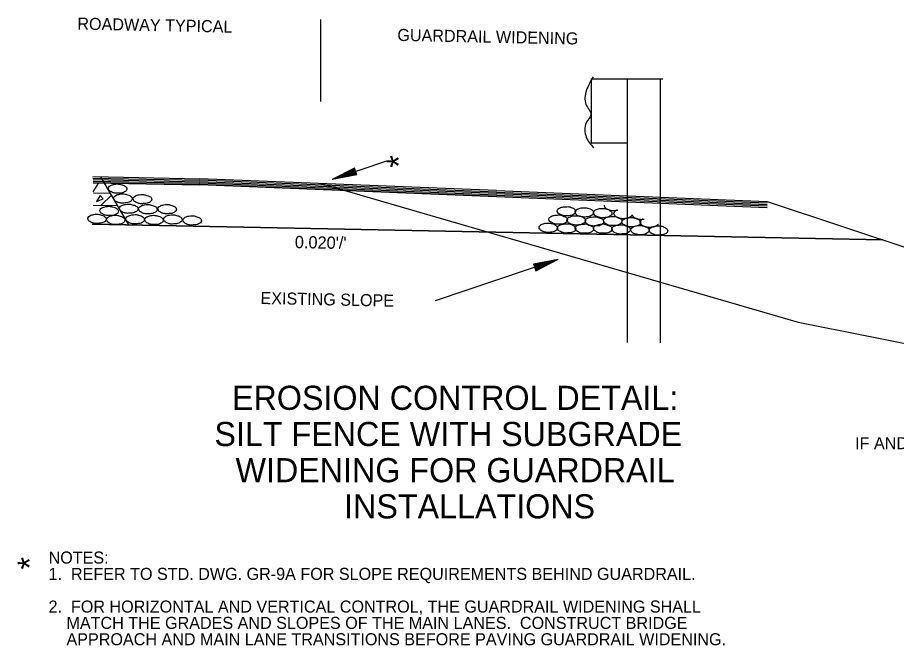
# Model space of a CAD drawing. Extents: x 1929624 to 1932070, y 596315 to 605533.
# Drawn here: x 1930679.3 to 1931116.5, y 605210.4 to 605522.8 of the extents above; entities that cross this region are included whole.
import ezdxf

# ---------------------------------------------------------------- set-up
doc = ezdxf.new("R2010")
doc.units = 0
doc.layers.add('Default', color=7, linetype='Continuous')
doc.layers.add('R_Border', color=7, linetype='Continuous')

msp = doc.modelspace()

# ---------------------------------------------------------------- linework, layer by layer
at = {"layer": 'Default'}
for p, q in [((1930964.72, 605492.28), (1930964.72, 605460.45)), ((1930964.72, 605492.28), (1931000.37, 605492.28)), ((1930982.56, 605492.28), (1930982.56, 605361.1)), ((1930998.94, 605492.14), (1930998.94, 605360.97)), ((1930964.72, 605460.45), (1930982.56, 605460.45)), ((1930862.9, 605451.4), (1930835.81, 605442.2)), ((1930846.84, 605447.99), (1930835.81, 605442.2)), ((1930846.97, 605447.71), (1930837.74, 605442.86)), ((1930847.08, 605447.37), (1930839.81, 605443.6)), ((1930848.05, 605444.54), (1930846.84, 605447.99)), ((1930716.81, 605443.72), (1930769.98, 605442.66)), ((1930716.81, 605442.98), (1930769.98, 605441.92)), ((1930734.6, 605419.73), (1930720.77, 605443.63)), ((1930848.05, 605444.54), (1930835.81, 605442.2)), ((1930847.97, 605444.8), (1930837.74, 605442.86)), ((1930847.83, 605445.12), (1930839.81, 605443.6)), ((1930847.13, 605447.1), (1930841.73, 605444.26)), ((1930847.73, 605445.42), (1930841.73, 605444.26)), ((1930847.25, 605446.84), (1930843.66, 605444.95)), ((1930847.61, 605445.73), (1930843.66, 605444.95)), ((1930847.34, 605446.53), (1930845.62, 605445.64)), ((1930847.57, 605446.03), (1930845.62, 605445.64)), ((1930716.84, 605442.24), (1930769.98, 605441.18)), ((1930716.86, 605441.5), (1930769.98, 605440.44)), ((1930716.89, 605440.76), (1930769.93, 605439.71)), ((1930716.89, 605440.67), (1930769.98, 605439.61)), ((1930716.98, 605436.19), (1930719.64, 605440.64)), ((1930917.5, 605433.8), (1930769.88, 605439.71)), ((1930917.55, 605435.28), (1930769.93, 605441.18)), ((1930917.55, 605434.54), (1930769.93, 605440.44)), ((1930917.6, 605436.75), (1930769.98, 605442.66)), ((1930917.6, 605436.02), (1930769.98, 605441.92)), ((1930917.5, 605433.7), (1930769.98, 605439.61)), ((1930717.01, 605435.6), (1930725.52, 605435.43)), ((1930720.87, 605429.47), (1930726.1, 605434.42)), ((1930917.5, 605434.54), (1931052.16, 605429.15)), ((1930917.54, 605435.28), (1931052.19, 605429.89)), ((1930917.56, 605436.02), (1931052.22, 605430.63)), ((1930917.6, 605436.75), (1931052.26, 605431.37)), ((1930917.48, 605433.8), (1931052.14, 605428.41)), ((1931052.26, 605431.37), (1931287.27, 605353.24)), ((1930716.89, 605429.55), (1930729.06, 605429.31)), ((1930887.28, 605381.99), (1930948.19, 605402.67)), ((1930935.95, 605400.34), (1930948.19, 605402.67)), ((1930935.95, 605400.34), (1930937.16, 605396.88)), ((1930936.03, 605400.08), (1930946.26, 605402.01)), ((1930936.17, 605399.76), (1930944.19, 605401.28)), ((1930936.27, 605399.46), (1930942.27, 605400.61)), ((1930936.39, 605399.14), (1930940.34, 605399.93)), ((1930936.43, 605398.84), (1930938.38, 605399.24)), ((1930936.66, 605398.34), (1930938.38, 605399.24)), ((1930936.75, 605398.04), (1930940.34, 605399.93)), ((1930936.87, 605397.78), (1930942.27, 605400.61)), ((1930936.92, 605397.5), (1930944.19, 605401.28)), ((1930937.03, 605397.17), (1930946.26, 605402.01)), ((1930937.16, 605396.88), (1930948.19, 605402.67))]:
    msp.add_line(p, q, dxfattribs=at)
msp.add_lwpolyline([(1930718.62, 605431.33), (1930721.86, 605432.66), (1930720.39, 605434.24), (1930718.62, 605431.33)], dxfattribs=at)
for points in [[(1930965.58, 605493.32), (1930962.23, 605486.4), (1930962.06, 605479.66), (1930964.47, 605474.47), (1930962.23, 605470.53), (1930962.23, 605463.28), (1930965.78, 605458.04)], [(1930729.05, 605440.07), (1930727.42, 605439.87), (1930725.55, 605439.28), (1930724.62, 605438.44), (1930724.47, 605437.85), (1930724.91, 605436.87), (1930725.46, 605436.38), (1930726.54, 605435.79), (1930728.11, 605435.44), (1930728.9, 605435.44), (1930730.13, 605435.49), (1930731.46, 605435.64), (1930732.54, 605436.08), (1930733.53, 605436.97), (1930733.67, 605437.56), (1930733.38, 605438.44), (1930732.64, 605439.03), (1930731.9, 605439.38), (1930730.82, 605439.72), (1930730.08, 605439.92), (1930729.05, 605440.07)], [(1930731.72, 605435.18), (1930730.1, 605434.98), (1930728.23, 605434.39), (1930727.24, 605433.56), (1930727.1, 605432.96), (1930727.54, 605431.98), (1930728.08, 605431.49), (1930729.16, 605430.9), (1930730.74, 605430.55), (1930731.57, 605430.55), (1930732.8, 605430.6), (1930734.13, 605430.75), (1930735.17, 605431.19), (1930736.2, 605432.08), (1930736.35, 605432.67), (1930736.05, 605433.56), (1930735.31, 605434.15), (1930734.58, 605434.49), (1930733.44, 605434.83), (1930732.75, 605435.03), (1930731.72, 605435.18)], [(1930741.38, 605434.86), (1930739.76, 605434.66), (1930737.89, 605434.07), (1930736.9, 605433.24), (1930736.76, 605432.64), (1930737.2, 605431.66), (1930737.74, 605431.17), (1930738.82, 605430.58), (1930740.4, 605430.23), (1930741.23, 605430.23), (1930742.47, 605430.28), (1930743.79, 605430.43), (1930744.83, 605430.87), (1930745.86, 605431.76), (1930746.01, 605432.35), (1930745.71, 605433.24), (1930744.97, 605433.83), (1930744.24, 605434.17), (1930743.1, 605434.51), (1930742.42, 605434.71), (1930741.38, 605434.86)], [(1930734.58, 605430.06), (1930732.96, 605429.86), (1930731.09, 605429.27), (1930730.11, 605428.44), (1930729.96, 605427.9), (1930730.4, 605426.91), (1930730.94, 605426.37), (1930732.02, 605425.78), (1930733.6, 605425.44), (1930734.44, 605425.44), (1930735.67, 605425.49), (1930736.99, 605425.63), (1930738.03, 605426.12), (1930739.06, 605426.96), (1930739.21, 605427.6), (1930738.91, 605428.49), (1930738.18, 605429.08), (1930737.44, 605429.42), (1930736.31, 605429.72), (1930735.62, 605429.96), (1930734.58, 605430.06)], [(1930744.1, 605429.84), (1930742.47, 605429.64), (1930740.6, 605429.05), (1930739.62, 605428.22), (1930739.47, 605427.67), (1930739.91, 605426.69), (1930740.46, 605426.15), (1930741.54, 605425.56), (1930743.11, 605425.21), (1930743.95, 605425.21), (1930745.18, 605425.26), (1930746.51, 605425.41), (1930747.54, 605425.9), (1930748.58, 605426.74), (1930748.72, 605427.38), (1930748.43, 605428.27), (1930747.69, 605428.86), (1930746.95, 605429.2), (1930745.82, 605429.5), (1930745.13, 605429.74), (1930744.1, 605429.84)], [(1930753.68, 605429.86), (1930752.05, 605429.66), (1930750.18, 605429.07), (1930749.25, 605428.23), (1930749.1, 605427.69), (1930749.54, 605426.71), (1930750.08, 605426.17), (1930751.17, 605425.58), (1930752.74, 605425.23), (1930753.53, 605425.23), (1930754.76, 605425.28), (1930756.09, 605425.43), (1930757.17, 605425.92), (1930758.15, 605426.76), (1930758.3, 605427.4), (1930758.01, 605428.28), (1930757.27, 605428.87), (1930756.53, 605429.22), (1930755.45, 605429.51), (1930754.71, 605429.76), (1930753.68, 605429.86)], [(1930724.82, 605428.97), (1930723.19, 605428.77), (1930721.32, 605428.18), (1930720.39, 605427.35), (1930720.24, 605426.76), (1930720.68, 605425.77), (1930721.22, 605425.28), (1930722.31, 605424.69), (1930723.88, 605424.35), (1930724.67, 605424.35), (1930725.9, 605424.39), (1930727.23, 605424.54), (1930728.31, 605424.98), (1930729.29, 605425.87), (1930729.44, 605426.46), (1930729.15, 605427.35), (1930728.41, 605427.94), (1930727.67, 605428.28), (1930726.59, 605428.63), (1930725.85, 605428.82), (1930724.82, 605428.97)], [(1930952.47, 605428.74), (1930950.84, 605428.64), (1930948.87, 605428.05), (1930947.84, 605427.12), (1930947.69, 605426.58), (1930948.19, 605425.59), (1930948.78, 605425.15), (1930949.91, 605424.61), (1930951.48, 605424.16), (1930952.32, 605424.16), (1930953.5, 605424.26), (1930954.83, 605424.41), (1930955.86, 605424.8), (1930956.75, 605425.64), (1930956.9, 605426.28), (1930956.6, 605427.17), (1930955.96, 605427.76), (1930955.27, 605428.15), (1930954.19, 605428.59), (1930953.5, 605428.74), (1930952.47, 605428.74)], [(1930961.28, 605428.22), (1930959.66, 605428.12), (1930957.74, 605427.43), (1930956.76, 605426.64), (1930956.61, 605426.1), (1930957.15, 605425.07), (1930957.59, 605424.53), (1930958.77, 605424.03), (1930960.25, 605423.69), (1930961.09, 605423.59), (1930962.32, 605423.64), (1930963.69, 605423.89), (1930964.68, 605424.33), (1930965.71, 605425.12), (1930965.86, 605425.76), (1930965.56, 605426.64), (1930964.83, 605427.28), (1930964.09, 605427.63), (1930963.01, 605427.97), (1930962.32, 605428.12), (1930961.28, 605428.22)], [(1930970.46, 605427.85), (1930968.84, 605427.8), (1930966.87, 605427.11), (1930965.88, 605426.22), (1930965.74, 605425.63), (1930966.28, 605424.65), (1930966.82, 605424.21), (1930967.9, 605423.71), (1930969.48, 605423.27), (1930970.31, 605423.22), (1930971.49, 605423.32), (1930972.82, 605423.57), (1930973.86, 605423.96), (1930974.84, 605424.75), (1930974.99, 605425.34), (1930974.69, 605426.22), (1930973.95, 605426.81), (1930973.26, 605427.31), (1930972.18, 605427.65), (1930971.49, 605427.8), (1930970.46, 605427.85)], [(1930971.08, 605429.44), (1930971.08, 605429.41), (1930971.08, 605429.34), (1930971.08, 605429.27), (1930971.16, 605429.01), (1930971.27, 605428.74), (1930971.43, 605428.49), (1930971.52, 605428.36), (1930971.63, 605428.24), (1930971.88, 605427.99), (1930972.17, 605427.8), (1930972.43, 605427.65), (1930972.7, 605427.52), (1930972.97, 605427.41), (1930973.25, 605427.31), (1930974.03, 605427.08), (1930974.82, 605426.91), (1930975.24, 605426.84), (1930975.45, 605426.82), (1930975.66, 605426.81), (1930976.25, 605426.84), (1930976.55, 605426.87), (1930976.84, 605426.91), (1930977.36, 605426.99), (1930977.88, 605427.09)], [(1930977.74, 605427.14), (1930977.44, 605427.02), (1930977.2, 605426.91), (1930976.96, 605426.79), (1930976.67, 605426.61), (1930976.41, 605426.39), (1930976.19, 605426.14), (1930976.08, 605426), (1930975.97, 605425.85), (1930975.9, 605425.72), (1930975.84, 605425.58), (1930975.82, 605425.45), (1930975.82, 605425.38), (1930975.83, 605425.31), (1930975.9, 605425.04), (1930976.02, 605424.78), (1930976.17, 605424.52), (1930976.27, 605424.4), (1930976.37, 605424.28), (1930976.62, 605424.03), (1930976.91, 605423.84), (1930977.17, 605423.69), (1930977.44, 605423.56), (1930977.71, 605423.44), (1930977.99, 605423.34), (1930978.77, 605423.12), (1930979.57, 605422.95), (1930980.4, 605422.85), (1930980.55, 605422.85), (1930980.7, 605422.86), (1930980.99, 605422.88), (1930981.58, 605422.95), (1930981.92, 605423), (1930982.25, 605423.06), (1930982.58, 605423.12), (1930982.91, 605423.2), (1930983.18, 605423.27), (1930983.44, 605423.36), (1930983.69, 605423.47), (1930983.94, 605423.59), (1930984.22, 605423.74), (1930984.48, 605423.9), (1930984.71, 605424.11), (1930984.82, 605424.24), (1930984.93, 605424.38), (1930985, 605424.5), (1930985.04, 605424.62)], [(1930718.79, 605425.06), (1930717.16, 605424.86), (1930715.29, 605424.27), (1930714.36, 605423.43), (1930714.21, 605422.84), (1930714.65, 605421.86), (1930715.2, 605421.37), (1930716.28, 605420.78), (1930717.85, 605420.43), (1930718.64, 605420.43), (1930719.87, 605420.48), (1930721.2, 605420.63), (1930722.28, 605421.07), (1930723.27, 605421.96), (1930723.41, 605422.55), (1930723.12, 605423.43), (1930722.38, 605424.03), (1930721.64, 605424.37), (1930720.56, 605424.71), (1930719.82, 605424.91), (1930718.79, 605425.06)], [(1930728.1, 605424.53), (1930726.47, 605424.33), (1930724.6, 605423.74), (1930723.67, 605422.9), (1930723.52, 605422.31), (1930723.96, 605421.33), (1930724.5, 605420.84), (1930725.59, 605420.24), (1930727.16, 605419.9), (1930727.95, 605419.9), (1930729.18, 605419.95), (1930730.51, 605420.1), (1930731.59, 605420.54), (1930732.57, 605421.43), (1930732.72, 605422.02), (1930732.43, 605422.9), (1930731.69, 605423.49), (1930730.95, 605423.84), (1930729.87, 605424.18), (1930729.13, 605424.38), (1930728.1, 605424.53)], [(1930737.74, 605424.85), (1930736.12, 605424.65), (1930734.25, 605424.06), (1930733.31, 605423.22), (1930733.16, 605422.63), (1930733.61, 605421.65), (1930734.15, 605421.15), (1930735.23, 605420.56), (1930736.81, 605420.22), (1930737.59, 605420.22), (1930738.82, 605420.27), (1930740.15, 605420.42), (1930741.23, 605420.86), (1930742.22, 605421.75), (1930742.37, 605422.34), (1930742.07, 605423.22), (1930741.33, 605423.81), (1930740.6, 605424.16), (1930739.51, 605424.5), (1930738.77, 605424.7), (1930737.74, 605424.85)], [(1930747.14, 605424.48), (1930745.52, 605424.29), (1930743.65, 605423.7), (1930742.71, 605422.86), (1930742.56, 605422.27), (1930743.01, 605421.29), (1930743.55, 605420.79), (1930744.63, 605420.2), (1930746.2, 605419.86), (1930746.99, 605419.86), (1930748.22, 605419.91), (1930749.55, 605420.06), (1930750.63, 605420.5), (1930751.62, 605421.38), (1930751.77, 605421.97), (1930751.47, 605422.86), (1930750.73, 605423.45), (1930749.99, 605423.8), (1930748.91, 605424.14), (1930748.17, 605424.34), (1930747.14, 605424.48)], [(1930756.51, 605424.75), (1930754.89, 605424.55), (1930753.02, 605423.96), (1930752.09, 605423.12), (1930751.94, 605422.58), (1930752.38, 605421.6), (1930752.92, 605421.06), (1930754, 605420.47), (1930755.58, 605420.12), (1930756.37, 605420.12), (1930757.6, 605420.17), (1930758.93, 605420.32), (1930760.01, 605420.81), (1930760.99, 605421.65), (1930761.14, 605422.29), (1930760.84, 605423.17), (1930760.11, 605423.76), (1930759.37, 605424.11), (1930758.29, 605424.4), (1930757.55, 605424.65), (1930756.51, 605424.75)], [(1930766.16, 605424.24), (1930764.53, 605424.04), (1930762.66, 605423.45), (1930761.73, 605422.61), (1930761.58, 605422.07), (1930762.03, 605421.09), (1930762.57, 605420.55), (1930763.65, 605419.96), (1930765.22, 605419.61), (1930766.01, 605419.61), (1930767.24, 605419.66), (1930768.57, 605419.81), (1930769.65, 605420.3), (1930770.64, 605421.14), (1930770.78, 605421.78), (1930770.49, 605422.66), (1930769.75, 605423.25), (1930769.01, 605423.6), (1930767.93, 605423.89), (1930767.19, 605424.14), (1930766.16, 605424.24)], [(1930948.39, 605424.63), (1930946.67, 605424.44), (1930944.75, 605423.94), (1930943.76, 605423.01), (1930943.62, 605422.47), (1930944.11, 605421.43), (1930944.7, 605420.99), (1930945.78, 605420.4), (1930947.36, 605420.01), (1930948.14, 605420.01), (1930949.37, 605420.11), (1930950.75, 605420.2), (1930951.79, 605420.7), (1930952.67, 605421.53), (1930952.82, 605422.17), (1930952.52, 605423.06), (1930951.79, 605423.65), (1930951.1, 605423.94), (1930950.01, 605424.39), (1930949.37, 605424.58), (1930948.39, 605424.63)], [(1930957.32, 605424.21), (1930955.7, 605424.16), (1930953.73, 605423.53), (1930952.75, 605422.59), (1930952.6, 605422.05), (1930953.14, 605421.02), (1930953.68, 605420.57), (1930954.76, 605420.08), (1930956.34, 605419.69), (1930957.17, 605419.59), (1930958.35, 605419.69), (1930959.68, 605419.93), (1930960.72, 605420.33), (1930961.7, 605421.11), (1930961.85, 605421.75), (1930961.55, 605422.64), (1930960.82, 605423.23), (1930960.13, 605423.67), (1930959.04, 605424.02), (1930958.35, 605424.16), (1930957.32, 605424.21)], [(1930966.42, 605423.71), (1930964.79, 605423.57), (1930962.82, 605423.02), (1930961.79, 605422.09), (1930961.64, 605421.55), (1930962.18, 605420.56), (1930962.73, 605420.12), (1930963.86, 605419.48), (1930965.38, 605419.14), (1930966.22, 605419.14), (1930967.4, 605419.24), (1930968.83, 605419.28), (1930969.81, 605419.78), (1930970.75, 605420.61), (1930970.89, 605421.25), (1930970.6, 605422.14), (1930969.91, 605422.73), (1930969.17, 605423.07), (1930968.14, 605423.42), (1930967.45, 605423.71), (1930966.42, 605423.71)], [(1930975.37, 605423.94), (1930973.75, 605423.75), (1930971.83, 605423.25), (1930970.85, 605422.32), (1930970.7, 605421.78), (1930971.24, 605420.74), (1930971.78, 605420.3), (1930972.86, 605419.71), (1930974.44, 605419.32), (1930975.22, 605419.32), (1930976.46, 605419.42), (1930977.78, 605419.51), (1930978.87, 605420.01), (1930979.8, 605420.84), (1930979.95, 605421.48), (1930979.65, 605422.37), (1930978.92, 605422.96), (1930978.18, 605423.25), (1930977.14, 605423.75), (1930976.41, 605423.89), (1930975.37, 605423.94)], [(1930984.67, 605423.3), (1930983.05, 605423.25), (1930981.08, 605422.61), (1930980.1, 605421.68), (1930979.95, 605421.14), (1930980.49, 605420.11), (1930981.03, 605419.66), (1930982.11, 605419.17), (1930983.69, 605418.78), (1930984.53, 605418.68), (1930985.71, 605418.78), (1930987.03, 605419.02), (1930988.07, 605419.42), (1930989.05, 605420.2), (1930989.2, 605420.84), (1930988.9, 605421.73), (1930988.17, 605422.32), (1930987.48, 605422.76), (1930986.39, 605423.11), (1930985.71, 605423.25), (1930984.67, 605423.3)], [(1930984.99, 605424.64), (1930985.08, 605424.43), (1930985.19, 605424.23), (1930985.32, 605424.04), (1930985.47, 605423.85), (1930985.73, 605423.6), (1930986.01, 605423.41), (1930986.27, 605423.27), (1930986.54, 605423.13), (1930986.81, 605423.02), (1930987.09, 605422.92), (1930987.87, 605422.7), (1930988.67, 605422.52), (1930989.09, 605422.46), (1930989.29, 605422.43), (1930989.5, 605422.43), (1930990.09, 605422.45), (1930990.68, 605422.52), (1930990.99, 605422.57)], [(1930990.57, 605422.71), (1930990.31, 605422.59), (1930990.18, 605422.53), (1930990.04, 605422.46), (1930989.75, 605422.27), (1930989.5, 605422.06), (1930989.27, 605421.81), (1930989.16, 605421.67), (1930989.06, 605421.52), (1930988.98, 605421.39), (1930988.93, 605421.25), (1930988.91, 605421.11), (1930988.9, 605421.05), (1930988.91, 605420.98), (1930988.99, 605420.71), (1930989.1, 605420.45), (1930989.26, 605420.19), (1930989.35, 605420.07), (1930989.45, 605419.95), (1930989.71, 605419.7), (1930989.99, 605419.51), (1930990.26, 605419.36), (1930990.52, 605419.23), (1930990.8, 605419.11), (1930991.08, 605419.01), (1930991.86, 605418.79), (1930992.65, 605418.62), (1930993.49, 605418.52), (1930993.64, 605418.52), (1930993.78, 605418.53), (1930994.08, 605418.55), (1930994.67, 605418.62), (1930995, 605418.67), (1930995.34, 605418.73), (1930995.67, 605418.79), (1930996, 605418.87), (1930996.26, 605418.94), (1930996.52, 605419.03), (1930996.78, 605419.14), (1930997.03, 605419.26), (1930997.31, 605419.41), (1930997.56, 605419.57), (1930997.8, 605419.78), (1930997.91, 605419.91), (1930997.96, 605419.97), (1930998.02, 605420.05), (1930998.06, 605420.12)], [(1930943.37, 605420.54), (1930941.75, 605420.49), (1930939.78, 605419.8), (1930938.84, 605418.92), (1930938.7, 605418.33), (1930939.19, 605417.34), (1930939.78, 605416.9), (1930940.81, 605416.41), (1930942.44, 605415.96), (1930943.22, 605415.91), (1930944.45, 605416.01), (1930945.78, 605416.26), (1930946.82, 605416.65), (1930947.75, 605417.44), (1930947.9, 605418.03), (1930947.6, 605418.92), (1930946.86, 605419.51), (1930946.18, 605420), (1930945.09, 605420.34), (1930944.4, 605420.49), (1930943.37, 605420.54)], [(1930952.47, 605420.25), (1930950.85, 605420.11), (1930948.88, 605419.51), (1930947.95, 605418.63), (1930947.8, 605418.04), (1930948.29, 605417.05), (1930948.78, 605416.61), (1930949.92, 605416.12), (1930951.44, 605415.63), (1930952.28, 605415.63), (1930953.51, 605415.73), (1930954.89, 605415.92), (1930955.87, 605416.27), (1930956.85, 605417.15), (1930957, 605417.74), (1930956.71, 605418.63), (1930955.97, 605419.22), (1930955.23, 605419.66), (1930954.2, 605420.06), (1930953.51, 605420.2), (1930952.47, 605420.25)], [(1930961.32, 605420.12), (1930959.7, 605419.92), (1930957.73, 605419.38), (1930956.75, 605418.5), (1930956.6, 605417.91), (1930957.14, 605416.92), (1930957.68, 605416.48), (1930958.76, 605415.89), (1930960.29, 605415.5), (1930961.13, 605415.5), (1930962.36, 605415.59), (1930963.69, 605415.69), (1930964.72, 605416.14), (1930965.7, 605417.02), (1930965.85, 605417.61), (1930965.56, 605418.5), (1930964.82, 605419.09), (1930964.08, 605419.43), (1930963, 605419.83), (1930962.36, 605420.07), (1930961.32, 605420.12)], [(1930970.58, 605420.13), (1930968.91, 605419.93), (1930966.94, 605419.39), (1930965.96, 605418.51), (1930965.81, 605417.92), (1930966.35, 605416.93), (1930966.89, 605416.49), (1930968.02, 605415.85), (1930969.55, 605415.5), (1930970.34, 605415.5), (1930971.57, 605415.55), (1930972.94, 605415.7), (1930973.98, 605416.14), (1930974.91, 605417.03), (1930975.06, 605417.62), (1930974.77, 605418.51), (1930974.03, 605419.1), (1930973.29, 605419.44), (1930972.26, 605419.79), (1930971.62, 605419.98), (1930970.58, 605420.13)], [(1930979.65, 605419.76), (1930977.93, 605419.56), (1930976.06, 605419.07), (1930975.03, 605418.14), (1930974.88, 605417.6), (1930975.42, 605416.56), (1930975.96, 605416.12), (1930977.09, 605415.53), (1930978.62, 605415.14), (1930979.41, 605415.14), (1930980.64, 605415.23), (1930982.06, 605415.33), (1930983.05, 605415.82), (1930983.98, 605416.66), (1930984.13, 605417.3), (1930983.84, 605418.19), (1930983.1, 605418.78), (1930982.41, 605419.07), (1930981.33, 605419.47), (1930980.69, 605419.71), (1930979.65, 605419.76)], [(1930988.93, 605419.38), (1930987.31, 605419.28), (1930985.39, 605418.6), (1930984.4, 605417.81), (1930984.25, 605417.27), (1930984.8, 605416.23), (1930985.24, 605415.69), (1930986.42, 605415.2), (1930987.9, 605414.86), (1930988.73, 605414.76), (1930989.96, 605414.81), (1930991.34, 605415.05), (1930992.32, 605415.5), (1930993.36, 605416.28), (1930993.51, 605416.92), (1930993.21, 605417.81), (1930992.47, 605418.45), (1930991.73, 605418.79), (1930990.65, 605419.14), (1930989.96, 605419.28), (1930988.93, 605419.38)], [(1930998.18, 605419.19), (1930996.56, 605419.05), (1930994.59, 605418.46), (1930993.65, 605417.57), (1930993.51, 605416.98), (1930994, 605416), (1930994.49, 605415.55), (1930995.62, 605415.06), (1930997.15, 605414.57), (1930997.98, 605414.57), (1930999.21, 605414.67), (1931000.59, 605414.86), (1931001.58, 605415.21), (1931002.56, 605416.09), (1931002.71, 605416.69), (1931002.41, 605417.57), (1931001.67, 605418.16), (1931000.94, 605418.6), (1930999.9, 605419), (1930999.21, 605419.15), (1930998.18, 605419.19)]]:
    msp.add_spline(points, degree=3, dxfattribs=at)
at = {"layer": 'R_Border'}
for p, q in [((1930830.08, 605481.03), (1930830.08, 605521.81)), ((1930716.33, 605420.1), (1931109.71, 605412.27)), ((1931109.71, 605412.27), (1930716.33, 605420.1))]:
    msp.add_line(p, q, dxfattribs=at)
msp.add_lwpolyline([(1930830.08, 605440.25), (1931067.62, 605371.32), (1931172.51, 605350.45), (1931225.36, 605348.85), (1931399.81, 605373.56)], dxfattribs=at)

# ---------------------------------------------------------------- texts
at = {"layer": 'Default'}
for s, height, rotation, p in [('ROADWAY TYPICAL', 6, 358.8537, (1930708.99, 605516.85)), ('GUARDRAIL WIDENING', 6, 358.8537, (1930868.18, 605511.23)), ('*', 12, 90, (1930874.91, 605448.14)), ("0.020'/'", 6.075, 358.8537, (1930817.17, 605408.17)), ('EXISTING SLOPE', 6, 358.8537, (1930800.1, 605380.32)), ('EROSION CONTROL DETAIL:', 12, 360, (1930785.98, 605327.65)), ('SILT FENCE WITH SUBGRADE', 12, 360, (1930777.22, 605309.65)), (' WIDENING FOR GUARDRAIL', 12, 360, (1930783.28, 605291.65)), (' INSTALLATIONS ', 12, 360, (1930837.28, 605273.65)), ('*', 12, 90, (1930691.3, 605248.24))]:
    msp.add_text(s, height=height, rotation=rotation, dxfattribs=at).set_placement(p)
for s, p in [('IF AND WHERE DIRECTED BY THE ENGINEER)', (1931095.96, 605308.06)), ('NOTES:', (1930694.71, 605251.17)), ('1.  REFER TO STD. DWG. GR-9A FOR SLOPE REQUIREMENTS BEHIND GUARDRAIL.', (1930694.71, 605243.04)), ('2.  FOR HORIZONTAL AND VERTICAL CONTROL, THE GUARDRAIL WIDENING SHALL', (1930694.71, 605226.79)), ('    MATCH THE GRADES AND SLOPES OF THE MAIN LANES.  CONSTRUCT BRIDGE', (1930694.71, 605218.66)), ('    APPROACH AND MAIN LANE TRANSITIONS BEFORE PAVING GUARDRAIL WIDENING.', (1930694.71, 605210.53))]:
    msp.add_text(s, height=6, dxfattribs=at).set_placement(p)

doc.saveas('drawing.dxf')
